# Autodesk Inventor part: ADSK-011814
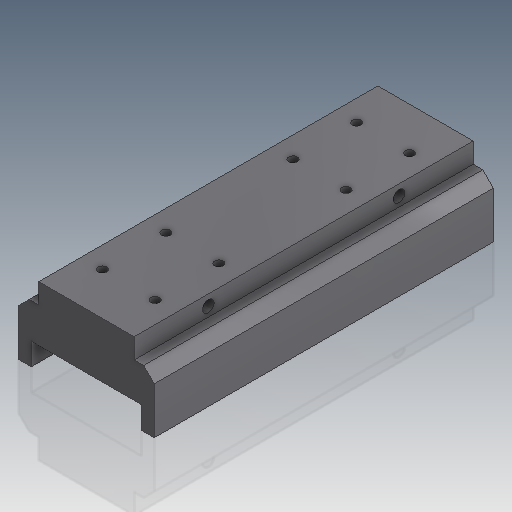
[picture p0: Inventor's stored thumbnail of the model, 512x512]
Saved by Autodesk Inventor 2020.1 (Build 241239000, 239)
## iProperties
Created: 1999-08
Part Number: ADSK-011814
Material: Acier inoxydable austénitique
Document SubType Name: Modeling
Designer: Autodesk
Density: 8.03 g/cm^3
Appearance: Metal-Steel(Polish)
Mass: 2007.89 g
Surface Area: 404.765 cm^2
Volume: 250.049 cm^3
Control State: 0
Master: False
Checked Out: False
Shininess: 0.0
Length Units: 11269
Angle Units: 11279
Time Units: 11290
Mass Units: 11286
Length Display Precision: 3
Angle Display Precision: 2
Compacted: True
Dimensions: 64x36,5x160 mm
Mass: 4,427 lb
DocNumber: ADSK-011814.ipt
Folder: 01 - Themengebiete\Simplification\01 - Packaging machine\
VDS_Category: 3D Komponenten
Density: 0.0
Volumn: 0.0
Area: 0.0
PropertySet Name: Model Information
Author: Autodesk
Revision Number: -
Title: wagon
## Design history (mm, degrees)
node "Extrusion1" dims "d13" = 160 (= e), "d14" = 0
node "Hole1" dims "d21" = 4.134, "d22" = 9.525, "d23" = 6.35, "d24" = 60 deg, "d25" = 12 (= Y), "d26" = 118 deg
node "Hole2" dims "d30" = 5.5 (= U_dia), "d31" = 9.525, "d32" = 6.35, "d33" = 60 deg, "d34" = 12 (= Y), "d35" = 118 deg
workplane "Work Plane1"
node "Solide1"
node "Corps solides"
node "Corps surfaciques"
sketch "Sketch1"
  geometry: L1 (-25.4, 0)-(25.4, 0) reference; L2 (0, 25.4)-(0, 0) reference; L3 (-22.5, 52)-(22.5, 52); L4 (22.5, 52)-(22.5, 42.5); L5 (22.5, 42.5)-(27, 42.5); L6 (27, 42.5)-(32, 37.5); L7 (32, 37.5)-(32, 15.5); L8 (32, 15.5)-(26, 15.5); L9 (26, 15.5)-(26, 26); L10 (26, 26)-(-26, 26); L11 (-26, 26)-(-26, 15.5); L12 (-26, 15.5)-(-32, 15.5); L13 (-32, 15.5)-(-32, 37.5); L14 (-32, 37.5)-(-27, 42.5); L15 (-27, 42.5)-(-22.5, 42.5); L16 (-22.5, 42.5)-(-22.5, 52)
  constraints: 32 end point, 9 parallel, 4 perpendicular, 2 collinear, 2 equal length, 2 horizontal, 1 midpoint, 1 vertical
  dimensions: "d0" = 15.5 distance between parallel lines of L12 L1 (= AO); "d1" = 32 distance between parallel lines of L13 L2 (= 0.5 x L); "d2" = 32 distance between parallel lines of L7 L2 (= 0.5 x L); "d4" = 22.5 distance between parallel lines of L2 L16 (= 0.5 x M); "d5" = 22.5 distance between parallel lines of L4 L2 (= 0.5 x M); "d6" = 52 distance between parallel lines of L3 L1 (= H); "d7" = 42.5 distance between parallel lines of L15 L1 (= R2); "d8" = 5 horizontal distance of L13.end L14.end; "d9" = 26 distance between parallel lines of L11 L2 (= 0.5 x O1); "d10" = 26 distance between parallel lines of L9 L2 (= 0.5 x O1); "d12" = 26 distance between parallel lines of L10 L1 (= 0.5 x O)
sketch "Sketch2"
  geometry: L1 (0, 0)-(45, 0) reference; L2 (45, 160)-(45, 0) reference; L3 (45, 160)-(0, 160) reference; L4 (0, 0)-(0, 160) reference; L5 (0, 80)-(45, 80); L6 (22.5, 0)-(22.5, 160); 8 further points
  constraints: 6 vertical alignment, 4 end point, 4 horizontal alignment, 4 midpoint
  dimensions: "d15" = 12.5 distance from line of point (10, 20) L6 (= 0.5 x AG); "d16" = 12.5 distance from line of point (35, 20) L6 (= 0.5 x AG); "d17" = 30 distance from line of point (10, 50) L5 (= 0.5 x G); "d18" = 60 distance from line of point (10, 20) L5 (= 0.5 x F); "d19" = 30 distance from line of point (10, 110) L5 (= 0.5 x G); "d20" = 60 distance from line of point (10, 140) L5 (= 0.5 x F)
sketch "Sketch3"
  geometry: L1 (160, 0)-(0, 0) reference; L2 (160, 9.5)-(0, 9.5) reference; L3 (80, 9.5)-(80, 0); 2 further points
  constraints: 2 end point, 2 midpoint, 1 horizontal alignment
  dimensions: "d27" = 45 distance from line of point (35, 4.5) L3 (= 0.5 x AB); "d28" = 45 distance from line of point (125, 4.5) L3 (= 0.5 x AB); "d29" = 5 distance from line of point (35, 4.5) L2 (= j)
other parameters: "AG" = 25 [user parameter; used in 2 equation terms], "AO" = 15.5 [user parameter; used in 1 equation term], "H" = 52 [user parameter; used in 1 equation term], "j" = 5 [user parameter; used in 1 equation term], "L" = 64 [user parameter; used in 2 equation terms], "M" = 45 [user parameter; used in 2 equation terms], "N_deep" = 8 [user parameter], "O" = 52 [user parameter; used in 1 equation term], "O1" = 52 [user parameter; used in 2 equation terms], "R2" = 42.5 [user parameter; used in 1 equation term], "U_dia" = 5.5 [user parameter; used in 1 equation term], "Y" = 12 [user parameter; used in 2 equation terms], "STROKE" = 914.4 [user parameter], "d36" = -80.01
